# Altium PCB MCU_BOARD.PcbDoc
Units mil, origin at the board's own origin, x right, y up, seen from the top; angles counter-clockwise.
Board outline 1735 x 1170 mil, 2 copper layers (Top Layer, Bottom Layer); 30 components, 93 nets, 101 pads, 0 vias.
Unrouted connection lines stored in the file: 63.
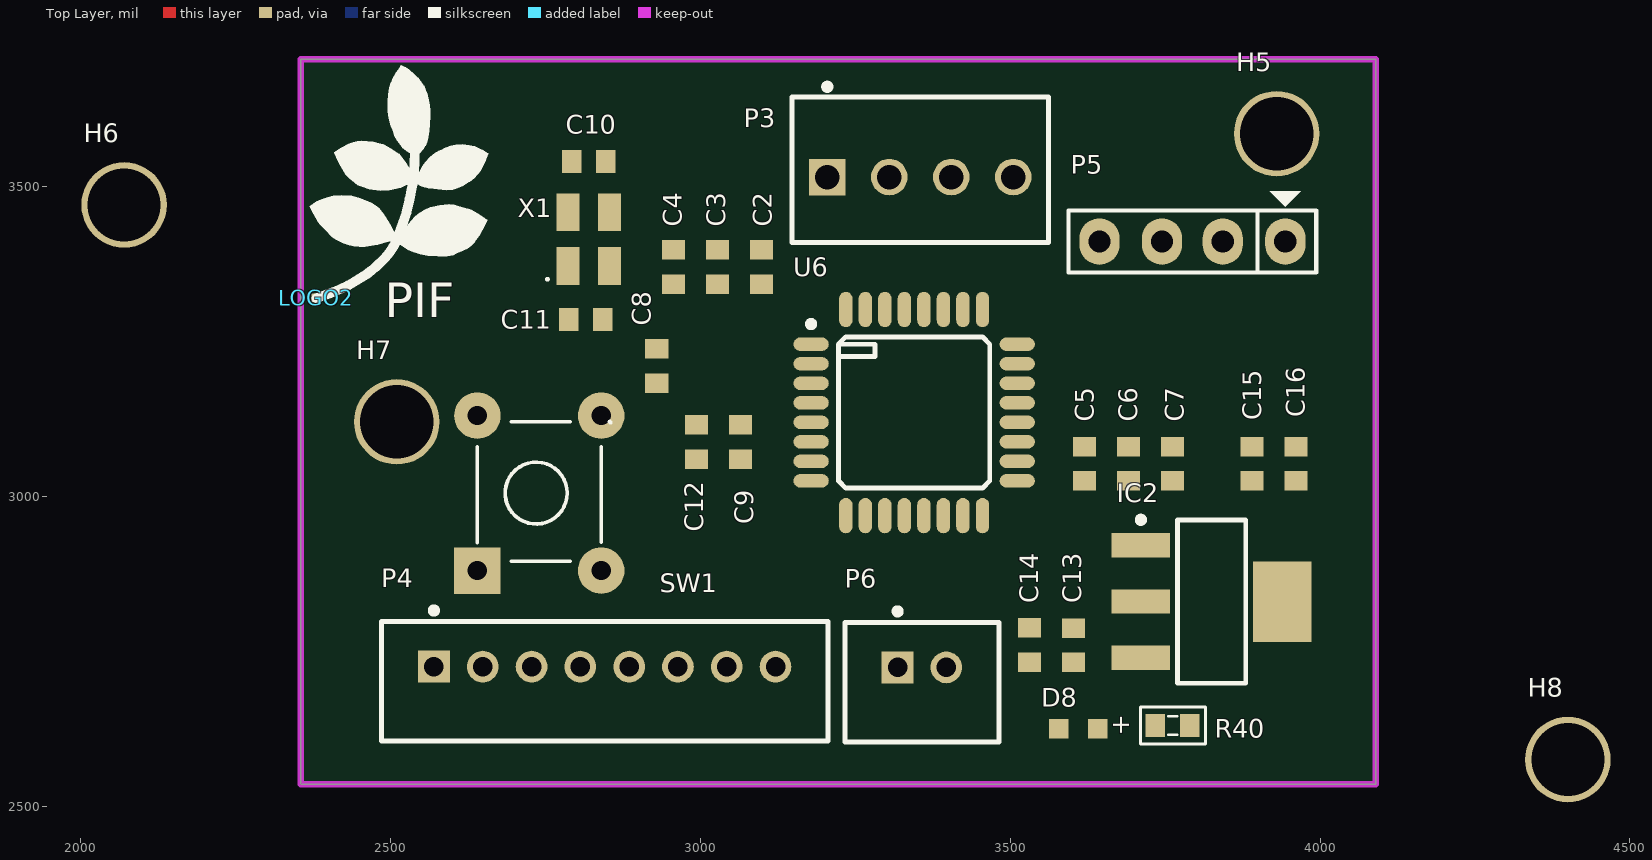
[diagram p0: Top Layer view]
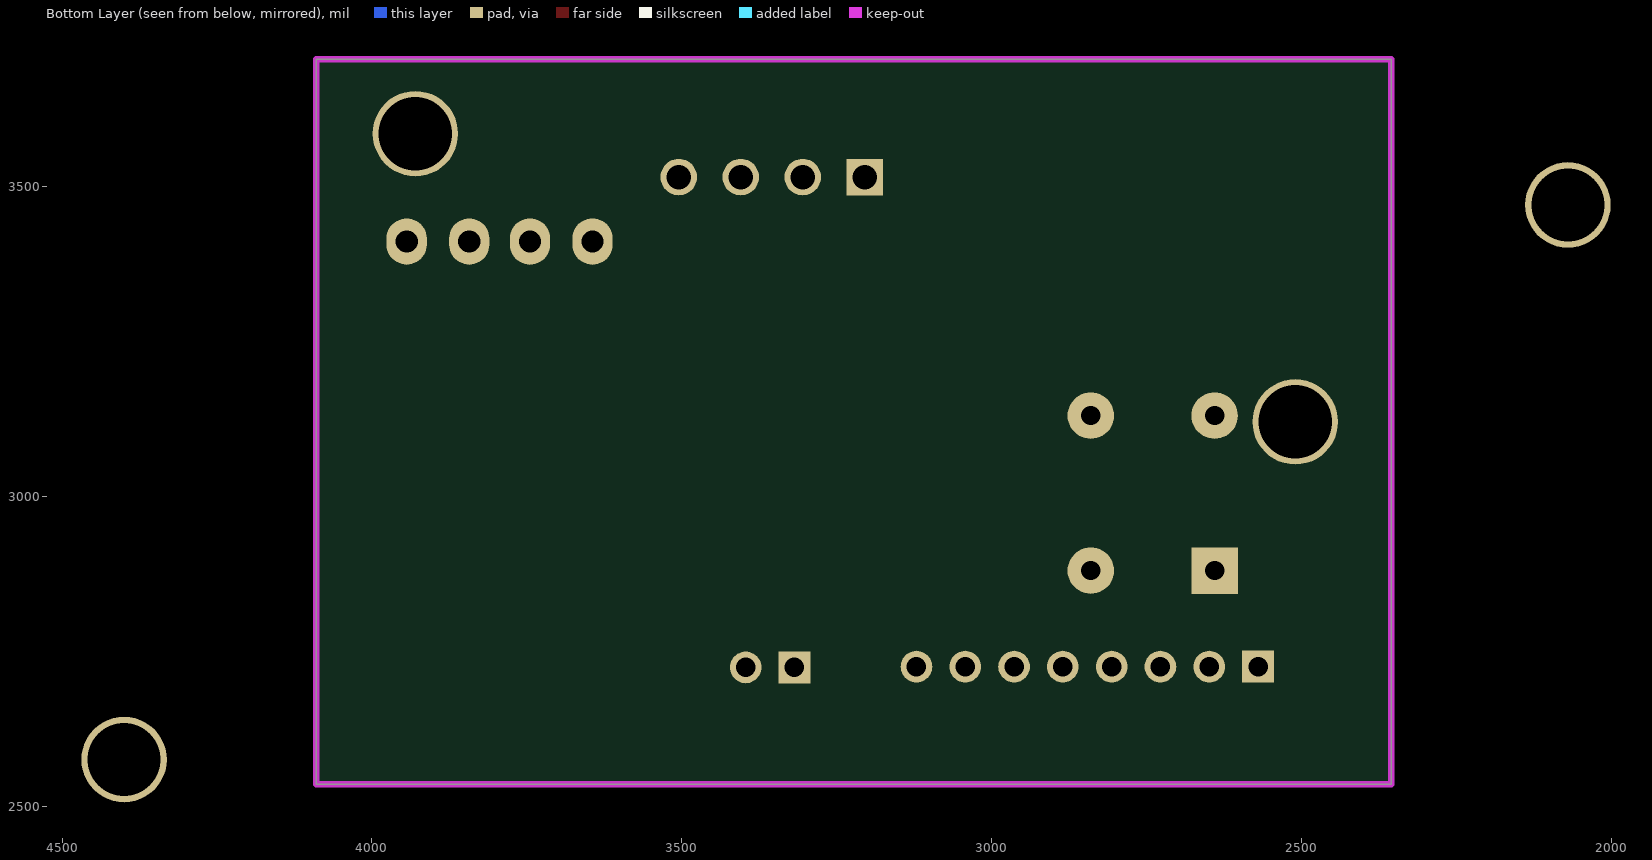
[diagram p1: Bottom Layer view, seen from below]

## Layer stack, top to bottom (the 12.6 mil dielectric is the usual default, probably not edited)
Top Solder: solder mask 0.4, Solder Resist, Dk 3.5
Top Layer: signal copper 1.4
Dielectric 1: dielectric 12.6, FR-4, Dk 4.8
Bottom Layer: signal copper 1.4
Bottom Solder: solder mask 0.4, Solder Resist, Dk 3.5

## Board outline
2355,2535 2355,3705 4090,3705 4090,2535

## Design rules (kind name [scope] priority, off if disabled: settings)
Clearance [All] p1: gap=8 ignorepadtopadclearanceinfootprint=FALSE
PolygonConnect [All] p1: connectstyle=Relief reliefconductorwidth=10 reliefentries=4 polygonreliefangle="90 Angle" airgapwidth=10
RoutingVias [All] p1: holewidth=28 width=50 viastyle="Through Hole" minholewidth=28 minwidth=50 maxholewidth=28 maxwidth=50
SolderMaskExpansion [All] p1: expansion=4 istentingtop=FALSE
Width [All] p1: maxlimit=30 minlimit=8 preferedwidth=10
30 further rules are at their usual default settings.

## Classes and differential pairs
component class CONTROL-PANEL: C2 C3 C4 C5 C6 C7 C8 C9 C10 C11 C12 C13 C14 D8 H5 H6 H7 H8 IC2 LOGO2 P3 P4 P5 P6 R40 SW1 U6 X1

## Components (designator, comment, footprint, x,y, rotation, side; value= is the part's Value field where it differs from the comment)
C2 "Cap Non-Pol SMD" CAP-SM-0603 3098.77,3369.85 r270 top value="100nF, 16V"
C3 "Cap Non-Pol SMD" CAP-SM-0603 3027.74,3369.85 r270 top value="100nF, 16V"
C4 "Cap Non-Pol SMD" CAP-SM-0603 2956.7,3369.85 r270 top value="4.7uF, 16V"
C5 "Cap Non-Pol SMD" CAP-SM-0603 3620,3052.56 r90 top value="100nF, 16V"
C6 "Cap Non-Pol SMD" CAP-SM-0603 3691.03,3052.56 r90 top value="100nF, 16V"
C7 "Cap Non-Pol SMD" CAP-SM-0603 3762.07,3052.56 r90 top value="4.7uF, 16V"
C8 "Cap Non-Pol SMD" CAP-SM-0603 2993.97,3087.56 r90 top value="10nF, 16V"
C9 "Cap Non-Pol SMD" CAP-SM-0603 3065,3087.56 r90 top value="1uF, 16V"
C10 "Cap Non-Pol SMD" CAP-SM-0603 2820,3540 r0 top value="10pF, 16V"
C11 "Cap Non-Pol SMD" CAP-SM-0603 2815,3285 r0 top value="10pF, 16V"
C12 "Cap Non-Pol SMD" CAP-SM-0603 2929.66,3210 r270 top value="100nF, 16V"
C13 "Cap Non-Pol SMD" CAP-SM-0603 3602.07,2759.71 r270 top value="1uF, 16V"
C14 "Cap Non-Pol SMD" CAP-SM-0603 3531.03,2759.83 r270 top value="100nF, 16V"
C15 "Cap Non-Pol SMD" CAP-SM-0603 3890,3052.44 r90 top value="100nF, 16V"
C16 "Cap Non-Pol SMD" CAP-SM-0603 3961.03,3052.44 r90 top value="1uF, 16V"
D8 "Yellow, 2V" WL-SMCW_0603_H=0.7mm 3609.81,2625 r0 top
H5 "Hole" "LO KHOAN 3MM" 3930,3585 r0 top
H6 "Hole" "LO KHOAN 3MM" 2070,3470 r0 top
H7 "Hole" "LO KHOAN 3MM" 2510,3120 r0 top
H8 "Hole" "LO KHOAN 3MM" 4400,2575 r0 top
IC2 "LM1117" SOT223-4N 3825,2830 r0 top value=LM317
LOGO2 "LOGO PIF" "PIF LOGO BIG SSTOP" 2369,3306 r0 top
P3 "61900411121" 61900411121 3354.84,3526.81 r180 top
P4 "62000811622" 62000811622 2845.66,2701.38 r180 top
P5 "DS3231 RTC MODULE" "DS3231 RTC MODULE" 3944,3410.99 r180 top
P6 "62000211622" 62000211622 3357.64,2700 r180 top
R40 "RESISTOR SMD" RES-SM-0603 3735,2630 r0 top value=1K
SW1 "SW" "Tact SW 4 pin" 2640,2880 r90 top value="Button chip 4 pin"
U6 "STM32F030K6T6" STM32F030K6T6 3345,3135 r0 top
X1 "XTAL 8MHz" "XTAL 3225" 2820,3415 r90 top value=16MHz

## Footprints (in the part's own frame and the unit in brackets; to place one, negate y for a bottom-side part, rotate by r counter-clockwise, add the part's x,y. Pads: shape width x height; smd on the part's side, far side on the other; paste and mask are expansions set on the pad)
61900411121 [mm] "2.54mm Male Locking Header, 4p"
  rect 1.5x1.5 hole 1: 1(3.81,0.3)
  round 1.5 hole 1: 2(1.27,0.3) 3(-1.27,0.3) 4(-3.81,0.3)
  silkscreen extent -5.25,-3.52 5.25,2.98, body extent -5.08,-2.9 5.08,2.9, height 11.53
62000211622 [mm] "2.00mm Male Vertical Shrouded Header, 2p"
  rect 1.3x1.3 hole 0.8: 1(1,-0.6)
  round 1.3 hole 0.8: 2(-1,-0.6)
  silkscreen extent -3.15,-3.02 3.15,2.45, body extent -3,-2.35 3,2.35, height 6.13
62000811622 [mm] "2.00mm Male Vertical Shrouded Header, 8p"
  rect 1.3x1.3 hole 0.8: 1(7,-0.6)
  round 1.3 hole 0.8: 2(5,-0.6) 3(3,-0.6) 4(1,-0.6) 5(-1,-0.6) 6(-3,-0.6) 7(-5,-0.6) 8(-7,-0.6)
  silkscreen extent -9.15,-3.02 9.15,2.45, body extent -9,-2.35 9,2.35, height 6.13
CAP-SM-0603 [mm] "SMD Ceramic Capacitor Size 0603"
  rect 0.8x0.95 smd: 1(-0.7,0) 2(0.7,0)
  body extent -0.85,-0.45 0.85,0.45, height 0.6
"DS3231 RTC MODULE" [mil]
  oval 65x75 hole 36: 1(0,0) 2(101,0) 3(199,0) 4(300,0)
  silkscreen extent -50,-81 350,50, body extent -48,-48 348,50, height 323
"LO KHOAN 3MM" [mil]
  round 138 hole 118.1: 1(0,0)
"PIF LOGO BIG SSTOP" [mil]
  rect 15x15 smd: 1(11,14)
  silkscreen extent 0,14 289,389
RES-SM-0603 [mm]
  rect 0.8x0.95 smd: 1(-0.014,0) 2(1.386,0)
  silkscreen extent -0.64,-0.76 2.03,0.76, body extent -0.11,-0.4 1.49,0.4, height 0.3
SOT223-4N [mm] "SOT223, 4-Leads, Body 6.5x3.5mm, Pitch 2.3mm, Lead Span 7mm, IPC Medium Density"
  rect 2.4x1 smd: 1(-2.9,2.3) 2(-2.9,0) 3(-2.9,-2.3)
  rect 2.4x3.3 smd: 4(2.9,0)
  silkscreen extent -3.02,-3.35 1.4,3.47, body extent -3.39,-3.27 3.5,3.23, height 1.72
STM32F030K6T6 [mm] "ARM Cortex M0 Microcontroller IC 32-Bit 48MHz 32KB FLASH, 32-LQFP"
  oval 1.45x0.55 smd: 1(-4.225,2.8) 2(-4.225,2) 3(-4.225,1.2) 4(-4.225,0.4) 5(-4.225,-0.4) 6(-4.225,-1.2) 7(-4.225,-2) 8(-4.225,-2.8) 17(4.225,-2.8) 18(4.225,-2) 19(4.225,-1.2) 20(4.225,-0.4) 21(4.225,0.4) 22(4.225,1.2) 23(4.225,2) 24(4.225,2.8)
  oval 0.55x1.45 smd: 9(-2.8,-4.225) 10(-2,-4.225) 11(-1.2,-4.225) 12(-0.4,-4.225) 13(0.4,-4.225) 14(1.2,-4.225) 15(2,-4.225) 16(2.8,-4.225) 25(2.8,4.225) 26(2,4.225) 27(1.2,4.225) 28(0.4,4.225) 29(-0.4,4.225) 30(-1.2,4.225) 31(-2,4.225) 32(-2.8,4.225)
  silkscreen extent -4.35,-3.1 3.1,3.75, body extent -4.6,-4.6 4.6,4.6, height 1.55
"Tact SW 4 pin" [mil] "SW button 4pin, 250 x250 mil"
  rect 75x75 hole 31: 1(0,0)
  round 75 hole 31: 2(250,-200) 3(250,0) 4(0,-200)
  silkscreen extent 15,-215 240,0, body extent -36,-220 276,24, height 276
WL-SMCW_0603_H=0.7mm [mm] "SMD Mono-color Chip LED, body 1.6x0.8mm"
  rect 0.8x0.8 smd: 1(-0.8,0) 2(0.8,0)
  body extent -0.8,-0.4 0.8,0.4, height 0.7
"XTAL 3225" [mm]
  rect 1.55x0.95 smd: 1(-1.1,-0.85) 2(1.1,-0.85) 3(1.1,0.85) 4(-1.1,0.85)
  silkscreen extent -1.7,1.65 -1.6,1.75, body extent -1.6,-1.25 1.6,1.25, height 0.55

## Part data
C2 C3 C4 C5 C6 C7 C8 C9 C10 C11 C12 C13 C14 C15 C16: "Capacitor"
D8: library part 150060YS75000, "WL-SMCW SMT Mono-color Chip LED Waterclear, size 0603, Yellow, 2V, 140deg", Emitting Color=Yellow, Forward Voltage typ.=2V, Operating Temperature="-40 to +85degC"
H5 H6 H7 H8: "Hole 3mm"
IC2: "Available in 1.8V, 2.5V, 2.85V, 3.3V, 5V, and  Adjustable Versions"
P3: "WR-WTB THT Male Vertical Locking Header, pitch 2.54mm, 4p", Contact Resistance=20mOhm, Operating Temperature="-40 to +105degC", Rated Current=3A, Withstanding Voltage=1000VAC, Working Voltage=250VAC
P4: "WR-WTB Male Vertical Shrouded Header, pitch 2mm, 8p", Contact Resistance=20mOhm, Operating Temperature="-25 to +85degC", Rated Current=2A, Withstanding Voltage=800VAC, Working Voltage=125VAC
P6: "WR-WTB Male Vertical Shrouded Header, pitch 2mm, 2p", Contact Resistance=20mOhm, Operating Temperature="-25 to +85degC", Rated Current=2A, Withstanding Voltage=800VAC, Working Voltage=125VAC
R40: "Resistor"
SW1: library part "Tact SW - 4Pin", "Switch button 4 pin"
U6: "ARM Cortex M0 Microcontroller IC 32-Bit 48MHz 32KB FLASH, 32-LQFP", Mfr=STMicroelectronics, Package / Case=32-LQFP
X1: library part XTAL

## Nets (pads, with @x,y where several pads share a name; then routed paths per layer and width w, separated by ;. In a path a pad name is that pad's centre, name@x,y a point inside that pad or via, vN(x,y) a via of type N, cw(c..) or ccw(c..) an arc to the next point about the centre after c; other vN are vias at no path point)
+3.3: C2.2 C3.2 C4.2 C5.2 C6.2 C7.2 C8.2 C9.2 C15.2 C16.2 IC2.2 IC2.4 P3.1 P5.3 R40.2 U6.1 U6.5 U6.17
+5: C13.2 C14.2 IC2.3 P6.2
BIT_A: 
BIT_A0: P4.1 U6.7
BIT_A1: P4.2 U6.8
BIT_A2: P4.3 U6.9
BIT_A3: P4.4 U6.10
BIT_B: 
BIT_C: 
BIT_D: 
DIGIT_1: P4.5 U6.11
DIGIT_2: P4.6 U6.12
DIGIT_3: P4.7 U6.13
DIGIT_4: P4.8 U6.14
GND: C2.1 C3.1 C4.1 C5.1 C6.1 C7.1 C8.1 C9.1 C10.1 C11.1 C12.1 C13.1 C14.1 C15.1 C16.1 D8.1 IC2.1 P3.3 P5.4 P6.1 SW1.1 SW1.3 U6.16 U6.32
I2C_SCL: P5.1 U6.19
I2C_SDA: P5.2 U6.20
NetC1_1: 
NetD1_1: 
NetD3_2: 
NetD3_3: 
NetD3_4: 
NetD3_6: 
NetD3_7: 
NetD3_9: 
NetD3_10: 
NetD4_2: 
NetD4_3: 
NetD4_4: 
NetD4_6: 
NetD4_7: 
NetD4_9: 
NetD4_10: 
NetD5_2: 
NetD5_3: 
NetD5_4: 
NetD5_6: 
NetD5_7: 
NetD5_9: 
NetD5_10: 
NetD6_2: 
NetD6_3: 
NetD6_4: 
NetD6_6: 
NetD6_7: 
NetD6_9: 
NetD6_10: 
NetD7_K: 
NetD8_2: D8.2 R40.1
NetIC1_3: 
NetIC1_7: 
NetP1_1: 
NetP1_2: 
NetP1_3: 
NetP1_4: 
NetP1_5: 
NetP1_6: 
NetP1_7: 
NetP1_8: 
NetR4_2: 
NetR5_2: 
NetR6_2: 
NetR7_2: 
NetR8_2: 
NetR9_2: 
NetR10_2: 
NetR11_2: 
NetR12_2: 
NetR13_2: 
NetR14_2: 
NetR15_2: 
NetR16_2: 
NetR17_2: 
NetR18_2: 
NetR19_2: 
NetR20_2: 
NetR21_2: 
NetR22_2: 
NetR23_2: 
NetR24_2: 
NetR25_2: 
NetR26_2: 
NetR27_2: 
NetR28_2: 
NetR29_2: 
NetR30_2: 
NetR31_2: 
NRST: C12.2 SW1.2 SW1.4 U6.4
OSC_IN: C10.2 U6.2 X1.3
OSC_OUT: C11.2 U6.3 X1.1
SWCLK: P3.2 U6.24
SWDIO: P3.4 U6.23
VCC7-20V: 
pads on no net: H5.1 H6.1 H7.1 H8.1 LOGO2.1 U6.6 U6.15 U6.18 U6.21 U6.22 U6.25 U6.26 U6.27 U6.28 U6.29 U6.30 U6.31 X1.2 X1.4

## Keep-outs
Keep-Out Layer:
  the board outline again, w10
